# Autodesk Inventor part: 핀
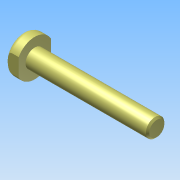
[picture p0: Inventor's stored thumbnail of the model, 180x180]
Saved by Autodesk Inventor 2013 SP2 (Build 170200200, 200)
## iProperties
Created: 2025-07
Part Number: 핀
Material: Generic
Document SubType Name: Modeling
Designer: a
Density: 1 g/cm^3
Author: a
변환 표준: STEP AP214IS
전처리기: Build: 200, Release: 2013 SP2 Update 6 - Date: Thu 07/17/2014
전송 단위: 밀리미터
불확실성: 0.01
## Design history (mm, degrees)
node "핀1"
node "솔리드1"
node "기준1"
